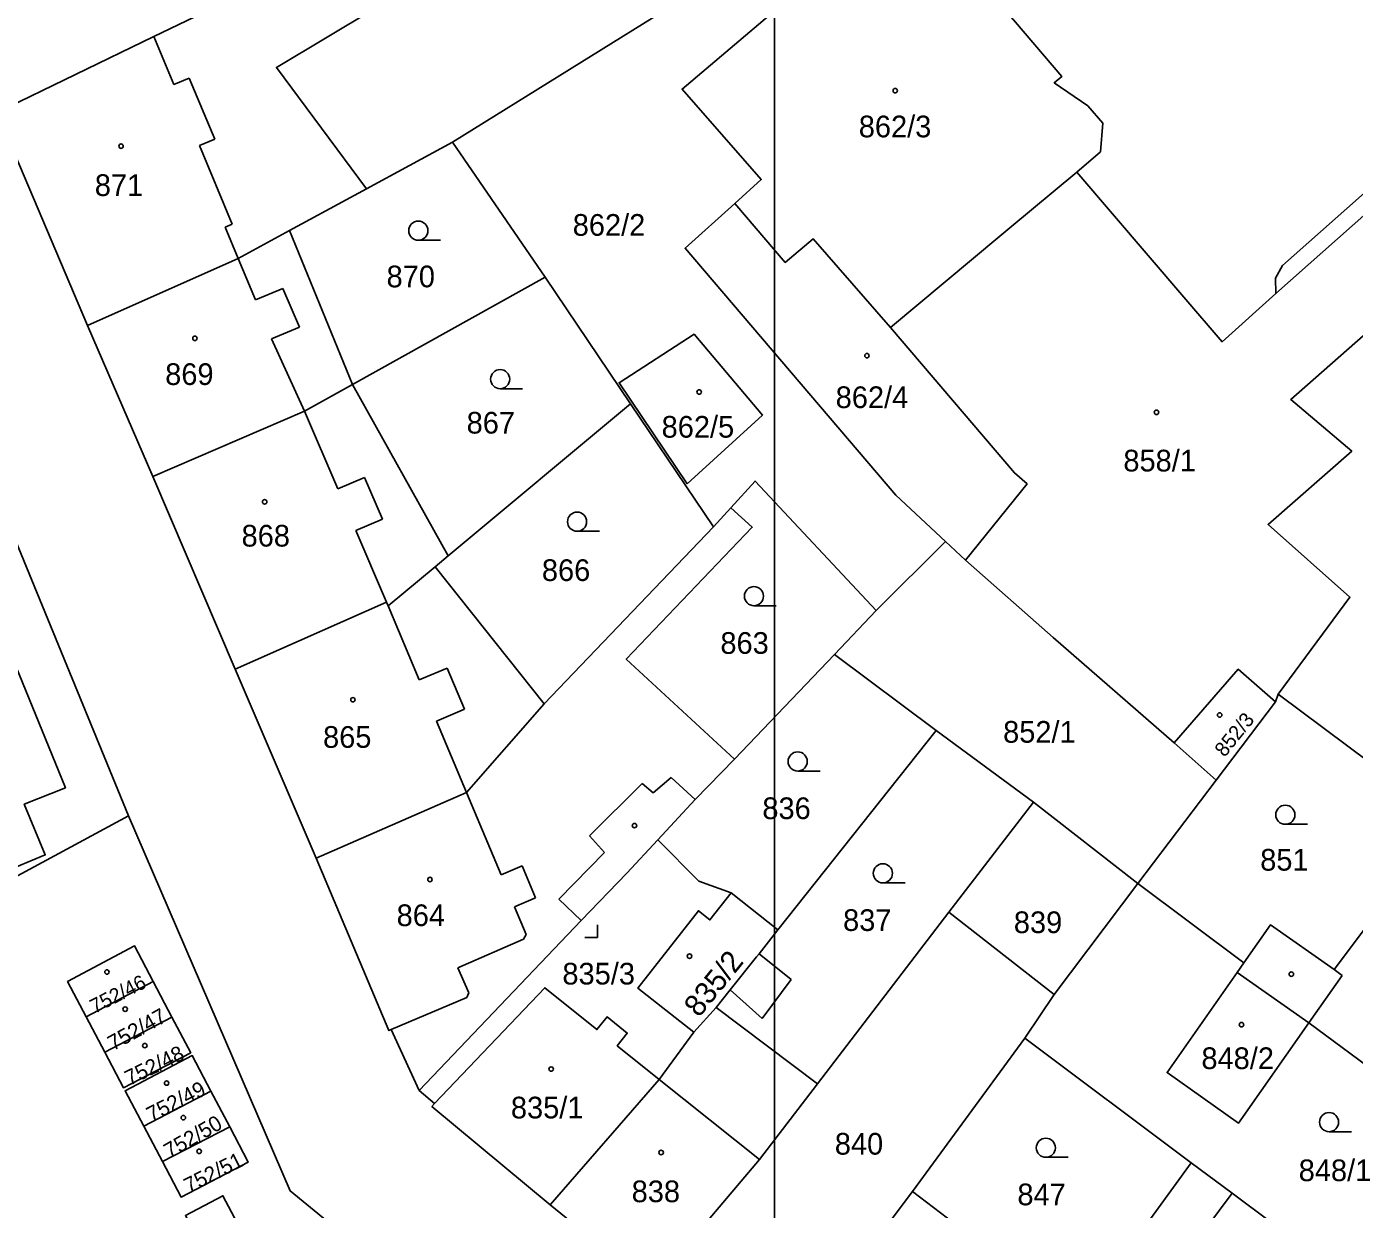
# Model space of a CAD drawing. Extents: x -496682 to -495907, y -1088575 to -1088018.
# Drawn here: x -496196 to -496091.9, y -1088306.8 to -1088214 of the extents above; entities that cross this region are included whole.
import ezdxf

# ---------------------------------------------------------------- set-up
doc = ezdxf.new("R2010")
doc.units = 0
for name, color, linetype in [('Hranice parcel', 7, 'Continuous'), ('Parcelní čísla', 7, 'Continuous'), ('Vnitřní kresba', 7, 'Continuous'), ('Vrstva 63', 7, 'Continuous'), ('Značky budov', 7, 'Continuous'), ('Značky kultur', 7, 'Continuous')]:
    doc.layers.add(name, color=color, linetype=linetype)

msp = doc.modelspace()

# ---------------------------------------------------------------- linework, layer by layer
at = {"layer": 'Hranice parcel'}
for p, q in [((-496162.6, -1088223.08), (-496138.52, -1088208.12)), ((-496198.35, -1088220.77), (-496191.24, -1088237.47)), ((-496169.35, -1088226.74), (-496162.6, -1088223.08)), ((-496162.6, -1088223.08), (-496155.35, -1088233.68)), ((-496169.35, -1088226.74), (-496175.38, -1088230.01)), ((-496170.44, -1088242.08), (-496175.38, -1088230.01)), ((-496155.35, -1088233.68), (-496170.44, -1088242.08)), ((-496155.35, -1088233.68), (-496148.66, -1088243.61)), ((-496191.24, -1088237.47), (-496186.12, -1088249.31)), ((-496170.44, -1088242.08), (-496162.94, -1088255.53)), ((-496148.66, -1088243.61), (-496162.94, -1088255.53)), ((-496148.66, -1088243.61), (-496142.14, -1088253.24)), ((-496188.02, -1088275.91), (-496199.66, -1088247.57)), ((-496186.12, -1088249.31), (-496179.65, -1088264.41)), ((-496142.14, -1088253.24), (-496140.78, -1088251.76)), ((-496155.43, -1088267.13), (-496142.14, -1088253.24)), ((-496129.39, -1088259.8), (-496123.95, -1088254.4)), ((-496122.37, -1088255.87), (-496123.95, -1088254.4)), ((-496162.94, -1088255.53), (-496163.98, -1088256.4)), ((-496155.43, -1088267.13), (-496163.98, -1088256.4)), ((-496132.65, -1088263.27), (-496129.39, -1088259.8)), ((-496140.49, -1088271.46), (-496132.65, -1088263.27)), ((-496132.65, -1088263.27), (-496124.69, -1088269.21)), ((-496179.65, -1088264.41), (-496173.29, -1088279.24)), ((-496097.87, -1088266.38), (-496098.08, -1088266.98)), ((-496098.08, -1088266.98), (-496102.73, -1088273.12)), ((-496137.09, -1088284.86), (-496124.69, -1088269.21)), ((-496124.69, -1088269.21), (-496117.05, -1088274.85)), ((-496102.73, -1088273.12), (-496106.03, -1088270.19)), ((-496102.73, -1088273.12), (-496108.86, -1088281.21)), ((-496123.68, -1088283.47), (-496117.05, -1088274.85)), ((-496117.05, -1088274.85), (-496108.86, -1088281.21)), ((-496219.91, -1088293.08), (-496188.02, -1088275.91)), ((-496137.09, -1088284.86), (-496140.75, -1088281.96)), ((-496115.43, -1088289.93), (-496108.86, -1088281.21)), ((-496100.55, -1088287.45), (-496108.86, -1088281.21)), ((-496152.52, -1088284.11), (-496165.22, -1088297.46)), ((-496133.98, -1088296.93), (-496123.68, -1088283.47)), ((-496123.68, -1088283.47), (-496115.43, -1088289.93)), ((-496101.08, -1088288.2), (-496100.55, -1088287.45)), ((-496101.08, -1088288.2), (-496095.45, -1088292.15)), ((-496191.33, -1088291.68), (-496186.08, -1088288.9)), ((-496184.61, -1088291.7), (-496186.08, -1088288.9)), ((-496117.73, -1088293.34), (-496115.43, -1088289.93)), ((-496143.68, -1088292.88), (-496141.93, -1088290.94)), ((-496133.98, -1088296.93), (-496141.93, -1088290.94)), ((-496191.33, -1088291.68), (-496189.88, -1088294.44)), ((-496189.88, -1088294.44), (-496184.61, -1088291.7)), ((-496079.66, -1088303.84), (-496095.45, -1088292.15)), ((-496143.68, -1088292.88), (-496146.4, -1088296.58)), ((-496117.73, -1088293.34), (-496126.53, -1088305.37)), ((-496104.68, -1088303.11), (-496117.73, -1088293.34)), ((-496154.95, -1088306.41), (-496146.4, -1088296.58)), ((-496186.82, -1088300.25), (-496181.56, -1088297.49)), ((-496180.08, -1088300.29), (-496181.56, -1088297.49)), ((-496165.22, -1088297.46), (-496164.02, -1088298.48)), ((-496186.82, -1088300.25), (-496185.36, -1088303.02)), ((-496185.36, -1088303.02), (-496180.08, -1088300.29)), ((-496113.5, -1088315.25), (-496104.68, -1088303.11)), ((-496118.15, -1088311.73), (-496126.53, -1088305.37)), ((-496154.95, -1088306.41), (-496147.01, -1088312.86))]:
    msp.add_line(p, q, dxfattribs=at)
for points in [[(-496135.52, -1088211.22), (-496134.74, -1088210.55), (-496130.01, -1088206.47), (-496126.43, -1088210.59), (-496123.42, -1088207.95), (-496118.45, -1088213.69), (-496114.82, -1088217.94), (-496115.42, -1088218.43), (-496112.79, -1088220.23), (-496111.62, -1088221.6), (-496111.79, -1088223.84), (-496113.66, -1088225.45)], [(-496179.86, -1088211.45), (-496179.28, -1088212.43), (-496171.58, -1088207.84), (-496168.73, -1088212.63), (-496176.42, -1088217.23), (-496169.35, -1088226.74)], [(-496140.48, -1088227.9), (-496138.4, -1088226.02), (-496144.6, -1088218.93), (-496135.52, -1088211.22)], [(-496179.86, -1088211.45), (-496182.82, -1088213.25), (-496186.02, -1088214.8), (-496198.35, -1088220.77)], [(-496071.36, -1088215.79), (-496073.4, -1088215.67), (-496077.32, -1088216.49), (-496080.87, -1088218.31), (-496083.31, -1088220.16), (-496097.53, -1088232.76), (-496098.07, -1088233.76), (-496098.04, -1088234.96), (-496102.26, -1088238.74), (-496105.26, -1088235.24), (-496113.66, -1088225.45)], [(-496063.85, -1088223.75), (-496067.02, -1088226.24), (-496072.13, -1088230.27), (-496073.39, -1088231.2), (-496083.78, -1088240.03), (-496087.92, -1088235.41), (-496096.87, -1088243.27), (-496092.09, -1088247.31), (-496098.65, -1088253.06), (-496092.23, -1088258.76), (-496097.87, -1088266.38)], [(-496113.66, -1088225.45), (-496118.91, -1088229.82), (-496119.69, -1088230.47), (-496128.26, -1088237.61)], [(-496123.95, -1088254.4), (-496127.85, -1088250.78), (-496144.37, -1088231.41), (-496140.48, -1088227.9)], [(-496140.48, -1088227.9), (-496136.51, -1088232.52), (-496134.32, -1088230.68), (-496128.26, -1088237.61)], [(-496175.38, -1088230.01), (-496179.42, -1088232.2), (-496191.24, -1088237.47)], [(-496144.21, -1088249.89), (-496149.54, -1088241.95), (-496143.66, -1088238.15), (-496138.31, -1088244.49), (-496144.21, -1088249.89)], [(-496128.26, -1088237.61), (-496118.54, -1088249.02), (-496117.55, -1088249.89), (-496122.37, -1088255.87)], [(-496170.44, -1088242.08), (-496174.22, -1088244.19), (-496186.12, -1088249.31)], [(-496140.78, -1088251.76), (-496138.88, -1088249.67), (-496129.39, -1088259.8)], [(-496140.78, -1088251.76), (-496139.1, -1088253.29), (-496148.98, -1088263.63), (-496140.49, -1088271.46)], [(-496122.37, -1088255.87), (-496115.51, -1088261.93), (-496106.03, -1088270.19)], [(-496163.98, -1088256.4), (-496167.65, -1088259.46), (-496167.78, -1088259.16), (-496179.65, -1088264.41)], [(-496224.27, -1088284.4), (-496221.97, -1088283.2), (-496218.31, -1088281.3), (-496217.38, -1088283.04), (-496208.49, -1088278.31), (-496215.03, -1088262.55), (-496203.26, -1088257.73), (-496201.7, -1088261.7), (-496198.45, -1088260.34), (-496192.96, -1088273.71), (-496196.19, -1088275), (-496194.54, -1088278.98), (-496202.44, -1088282.27), (-496202.01, -1088283.23), (-496220.05, -1088292.84)], [(-496106.03, -1088270.19), (-496100.99, -1088264.42), (-496098.08, -1088266.98)], [(-496097.87, -1088266.38), (-496085.29, -1088275.75), (-496084.66, -1088276.22)], [(-496173.29, -1088279.24), (-496161.51, -1088274.08), (-496155.43, -1088267.13)], [(-496140.49, -1088271.46), (-496143.57, -1088274.63), (-496146.52, -1088277.8)], [(-496188.02, -1088275.91), (-496175.34, -1088305.32), (-496115.85, -1088354.08), (-496107.5, -1088361.45)], [(-496084.66, -1088276.22), (-496093.48, -1088287.97), (-496098.46, -1088284.46), (-496100.55, -1088287.45)], [(-496146.52, -1088277.8), (-496148.95, -1088280.41), (-496152.52, -1088284.11)], [(-496140.75, -1088281.96), (-496143.3, -1088281.03), (-496146.52, -1088277.8)], [(-496173.29, -1088279.24), (-496167.59, -1088292.75), (-496167.42, -1088292.68), (-496165.22, -1088297.46)], [(-496140.75, -1088281.96), (-496142.42, -1088284.07), (-496143.32, -1088283.36), (-496148.07, -1088289.43), (-496143.68, -1088292.88)], [(-496141.93, -1088290.94), (-496140.84, -1088289.57), (-496138.76, -1088286.97), (-496138.57, -1088286.73), (-496137.09, -1088284.86)], [(-496186.08, -1088288.9), (-496187.54, -1088286.12), (-496192.79, -1088288.91), (-496191.33, -1088291.68)], [(-496095.45, -1088292.15), (-496100.96, -1088300), (-496106.57, -1088296.04), (-496101.08, -1088288.2)], [(-496146.4, -1088296.58), (-496149.69, -1088293.94), (-496148.9, -1088292.95), (-496150.49, -1088291.68), (-496151.28, -1088292.67), (-496155.37, -1088289.39), (-496164.02, -1088298.48)], [(-496189.88, -1088294.44), (-496188.41, -1088297.23), (-496183.13, -1088294.49), (-496184.61, -1088291.7)], [(-496181.56, -1088297.49), (-496183.02, -1088294.71), (-496188.28, -1088297.47), (-496186.82, -1088300.25)], [(-496147.01, -1088312.86), (-496138.54, -1088302.87), (-496133.98, -1088296.93)], [(-496164.02, -1088298.48), (-496164.23, -1088298.7), (-496154.95, -1088306.41)], [(-496185.36, -1088303.02), (-496183.89, -1088305.81), (-496178.62, -1088303.07), (-496180.08, -1088300.29)], [(-496092.02, -1088312.57), (-496101.47, -1088305.51), (-496104.68, -1088303.11)], [(-496181.09, -1088311.98), (-496178.12, -1088310.44), (-496180.61, -1088305.71), (-496183.56, -1088307.26), (-496181.09, -1088311.98)], [(-496126.53, -1088305.37), (-496130.83, -1088311.08), (-496137.88, -1088320.43)]]:
    msp.add_lwpolyline(points, dxfattribs=at)
at = {"layer": 'Vnitřní kresba'}
for p, q in [((-496184.45, -1088218.56), (-496186.02, -1088214.8)), ((-496183.25, -1088218.06), (-496184.45, -1088218.56)), ((-496181.25, -1088222.85), (-496183.25, -1088218.06)), ((-496098.04, -1088234.96), (-496082.47, -1088221.14)), ((-496182.45, -1088223.36), (-496181.25, -1088222.85)), ((-496179.88, -1088229.52), (-496182.45, -1088223.36)), ((-496180.43, -1088229.75), (-496179.88, -1088229.52)), ((-496179.42, -1088232.2), (-496180.43, -1088229.75)), ((-496178.06, -1088235.46), (-496179.42, -1088232.2)), ((-496175.91, -1088234.57), (-496178.06, -1088235.46)), ((-496174.62, -1088237.6), (-496175.91, -1088234.57)), ((-496176.8, -1088238.51), (-496174.62, -1088237.6)), ((-496174.22, -1088244.19), (-496176.8, -1088238.51)), ((-496174.22, -1088244.19), (-496171.6, -1088250.28)), ((-496171.6, -1088250.28), (-496169.51, -1088249.38)), ((-496169.51, -1088249.38), (-496168.1, -1088252.65)), ((-496168.1, -1088252.65), (-496170.2, -1088253.55)), ((-496170.2, -1088253.55), (-496167.78, -1088259.16)), ((-496167.65, -1088259.46), (-496165.22, -1088265.25)), ((-496165.22, -1088265.25), (-496163.03, -1088264.33)), ((-496163.03, -1088264.33), (-496161.68, -1088267.56)), ((-496161.68, -1088267.56), (-496163.87, -1088268.48)), ((-496163.87, -1088268.48), (-496161.51, -1088274.08)), ((-496151.86, -1088277.47), (-496147.73, -1088273.39)), ((-496147.73, -1088273.39), (-496146.88, -1088274.11)), ((-496146.88, -1088274.11), (-496145.47, -1088272.9)), ((-496145.47, -1088272.9), (-496143.57, -1088274.63)), ((-496161.51, -1088274.08), (-496158.8, -1088280.53)), ((-496150.7, -1088278.8), (-496151.86, -1088277.47)), ((-496154.26, -1088282.46), (-496150.7, -1088278.8)), ((-496158.8, -1088280.53), (-496157.14, -1088279.83)), ((-496157.14, -1088279.83), (-496156.09, -1088282.34)), ((-496156.09, -1088282.34), (-496157.75, -1088283.04)), ((-496157.75, -1088283.04), (-496156.84, -1088285.21)), ((-496152.52, -1088284.11), (-496154.26, -1088282.46)), ((-496156.84, -1088285.21), (-496157.03, -1088285.58)), ((-496157.03, -1088285.58), (-496162.2, -1088287.82)), ((-496136.04, -1088288.75), (-496138.57, -1088286.73)), ((-496162.2, -1088287.82), (-496161.32, -1088289.78)), ((-496092.84, -1088288.43), (-496095.45, -1088292.15)), ((-496093.48, -1088287.97), (-496092.84, -1088288.43)), ((-496138.33, -1088291.8), (-496136.04, -1088288.75)), ((-496161.48, -1088290.17), (-496167.42, -1088292.68)), ((-496161.32, -1088289.78), (-496161.48, -1088290.17)), ((-496140.84, -1088289.57), (-496138.33, -1088291.8)), ((-496138.54, -1088302.87), (-496146.4, -1088296.58)), ((-496101.47, -1088305.51), (-496103.46, -1088308.16))]:
    msp.add_line(p, q, dxfattribs=at)
at = {"layer": 'Vrstva 63'}
msp.add_lwpolyline([(-496137.35, -1088164.24), (-496137.35, -1088461.24), (-496557.35, -1088461.24), (-496557.35, -1088164.24)], close=True, dxfattribs=at)
at = {"layer": 'Značky budov'}
for centre in [(-496127.89, -1088219.05), (-496188.6, -1088223.4), (-496182.81, -1088238.47), (-496130.11, -1088239.83), (-496143.27, -1088242.68), (-496107.4, -1088244.27), (-496177.34, -1088251.29), (-496170.42, -1088266.81), (-496102.45, -1088268.01), (-496148.34, -1088276.68), (-496164.38, -1088280.91), (-496144.02, -1088286.92), (-496189.71, -1088288.16), (-496096.83, -1088288.33), (-496188.28, -1088291.07), (-496100.74, -1088292.29), (-496186.74, -1088293.93), (-496154.87, -1088295.77), (-496185.03, -1088296.87), (-496183.72, -1088299.58), (-496182.48, -1088302.22), (-496146.25, -1088302.31)]:
    msp.add_circle(centre, 0.175, dxfattribs=at)
at = {"layer": 'Značky kultur'}
for p, q in [((-496165.29, -1088230.78), (-496163.54, -1088230.78)), ((-496158.87, -1088242.42), (-496157.12, -1088242.42)), ((-496152.84, -1088253.6), (-496151.09, -1088253.6)), ((-496138.97, -1088259.44), (-496137.22, -1088259.44)), ((-496135.54, -1088272.4), (-496133.79, -1088272.4)), ((-496097.3, -1088276.58), (-496095.55, -1088276.58)), ((-496128.86, -1088281.17), (-496127.11, -1088281.17)), ((-496151.23, -1088285.45), (-496151.23, -1088284.45)), ((-496152.23, -1088285.45), (-496151.23, -1088285.45)), ((-496093.87, -1088300.68), (-496092.12, -1088300.68)), ((-496116.08, -1088302.69), (-496114.33, -1088302.69))]:
    msp.add_line(p, q, dxfattribs=at)
for centre in [(-496165.29, -1088230.03), (-496158.87, -1088241.67), (-496152.84, -1088252.85), (-496138.97, -1088258.69), (-496135.54, -1088271.65), (-496097.3, -1088275.83), (-496128.86, -1088280.42), (-496093.87, -1088299.93), (-496116.08, -1088301.94)]:
    msp.add_circle(centre, 0.75, dxfattribs=at)

# ---------------------------------------------------------------- texts
at = {"layer": 'Parcelní čísla'}
for s, p in [('862/3', (-496130.75, -1088222.71)), ('871', (-496190.66, -1088227.31)), ('862/2', (-496153.18, -1088230.43)), ('870', (-496167.78, -1088234.47)), ('869', (-496185.14, -1088242.13)), ('862/4', (-496132.56, -1088243.94)), ('867', (-496161.5, -1088245.94)), ('862/5', (-496146.21, -1088246.26)), ('858/1', (-496110, -1088248.91)), ('868', (-496179.15, -1088254.8)), ('866', (-496155.6, -1088257.5)), ('863', (-496141.6, -1088263.21)), ('852/1', (-496119.43, -1088270.18)), ('865', (-496172.76, -1088270.58)), ('836', (-496138.31, -1088276.17)), ('851', (-496099.27, -1088280.21)), ('864', (-496166.99, -1088284.56)), ('837', (-496131.98, -1088284.94)), ('839', (-496118.59, -1088285.11)), ('835/3', (-496153.99, -1088289.14)), ('848/2', (-496103.88, -1088295.77)), ('835/1', (-496158.03, -1088299.64)), ('840', (-496132.63, -1088302.48)), ('848/1', (-496096.25, -1088304.56)), ('838', (-496148.56, -1088306.21)), ('847', (-496118.31, -1088306.45))]:
    msp.add_text(s, height=1.7, dxfattribs=at).set_placement(p)
for s, height, rotation, p in [('852/3', 1.139, 51, (-496102.06, -1088271.37)), ('835/2', 1.7, 51, (-496143.28, -1088291.79)), ('752/46', 1.139, 27, (-496190.67, -1088291.45)), ('752/47', 1.2, 29, (-496189.22, -1088294.37)), ('752/48', 1.2, 26, (-496187.94, -1088297.1)), ('752/49', 1.2, 27, (-496186.22, -1088299.96)), ('752/50', 1.2, 30, (-496184.8, -1088302.82)), ('752/51', 1.2, 27, (-496183.28, -1088305.54))]:
    msp.add_text(s, height=height, rotation=rotation, dxfattribs=at).set_placement(p)

doc.saveas('drawing.dxf')
